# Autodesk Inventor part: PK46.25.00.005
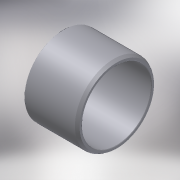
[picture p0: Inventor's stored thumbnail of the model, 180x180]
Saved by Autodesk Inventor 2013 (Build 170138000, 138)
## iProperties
Created: 2005-05
Part Number: PK46.25.00.005
Material: Steel, Mild
Document SubType Name: Modeling
Designer: PVitaliy
Manufacturer: Standard
Standards Organization: Custom
Density: 7.86 g/cm^3
Mass: 642.301 g
Surface Area: 351.265 cm^2
Volume: 81.7177 cm^3
Author: PVitaliy
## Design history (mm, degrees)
sketch "Эскиз2"
  geometry: L1 (0, 0)-(45.09, 0); L2 (0, 45)-(58.536, 45); L3 (0, 45)-(0, 40); L4 (0, 40)-(62, 40); L5 (62, 40)-(62, 43); L6 (58.536, 45)-(62, 43)
  constraints: 12 end point, 3 horizontal, 2 vertical, 1 point on line, 1 other
  dimensions: "d0" = 90 diameter of L2 L1; "d1" = 80 diameter of L4 L1; "d3" = 62 distance of L3.end L4.end; "d4" = 30 deg angle of L6 L2; "d5" = 86 diameter of L5.end L1
revolve "Вращение1" sketch "Эскиз2" stored, may be unused: angle "d6" = 90 deg
chamfer "Фаска1" distance "d7" = 0.5; stored, may be unused: second distance "d8" = 2, angle "d9" = 45 deg
body "Solid1"
